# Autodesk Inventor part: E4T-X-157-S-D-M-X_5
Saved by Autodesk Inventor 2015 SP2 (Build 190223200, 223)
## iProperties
Created: 2016-05
Part Number: E4T-X-157-S-D-M-X_5
Material: Allgemein
Document SubType Name: Modeling
Designer: ryll
Density: 1 g/cm^3
Appearance: Vorgabe
Author: ryll
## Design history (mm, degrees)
node "E4T-X-157-S-D-M-X_51"
node "E4T-X-157-S-D-M-X_5"
node "Basis1"
